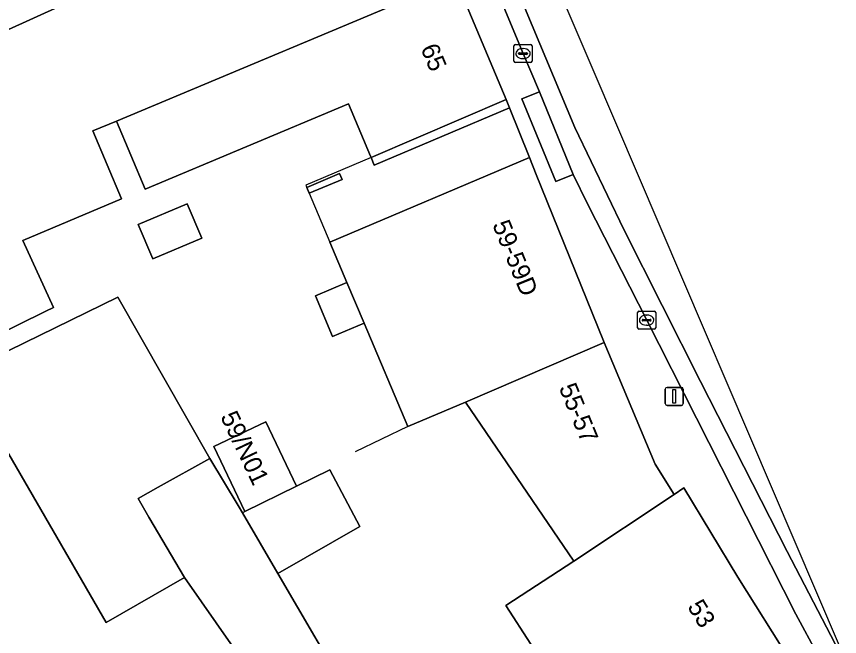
# Model space of a CAD drawing. Extents: x 159371 to 159986, y 382987 to 383597.
# Drawn here: x 159937.11 to 159982.64, y 383297.7 to 383332.01 of the extents above; entities that cross this region are included whole.
import ezdxf

# ---------------------------------------------------------------- set-up
doc = ezdxf.new("R2010")
doc.units = 0
for name, color, linetype in [('IMGEO_Erf', 7, 'Continuous'), ('IMGEO_Kolk', 7, 'Continuous'), ('IMGEO_Lichtmast', 7, 'Continuous'), ('IMGEO_Muur', 7, 'Continuous'), ('IMGEO_Pand', 7, 'Continuous'), ('IMGEO_Pand_nummerreeks', 7, 'Continuous'), ('IMGEO_Pand_overbouw', 7, 'Continuous'), ('IMGEO_Rijbaan_lokaal_gesloten', 7, 'Continuous'), ('IMGEO_Rijbaan_lokaal_open', 7, 'Continuous'), ('IMGEO_Voetpad_open', 7, 'Continuous')]:
    doc.layers.add(name, color=color, linetype=linetype)

msp = doc.modelspace()

# ---------------------------------------------------------------- linework, layer by layer
at = {"layer": 'IMGEO_Erf'}
for points in [[(159929.674, 383336.71), (159932.987, 383329.817), (159933.064, 383329.657), (159939.633, 383332.626)], [(159966.951, 383295.149), (159964.186, 383299.423), (159967.948, 383301.873), (159961.953, 383310.678), (159958.755, 383309.324), (159956.332, 383315.043), (159954.597, 383314.308), (159953.652, 383316.559), (159955.38, 383317.291), (159954.438, 383319.517), (159965.489, 383324.198), (159964.378, 383326.953), (159956.901, 383323.786), (159956.726, 383324.201), (159956.696, 383324.274), (159955.478, 383327.179), (159944.228, 383322.46), (159942.64, 383326.223), (159941.338, 383325.677), (159942.926, 383321.914), (159937.464, 383319.623), (159939.155, 383315.913), (159938.725, 383315.702), (159934.236, 383313.5)], [(159934.071, 383312.263), (159942.713, 383316.486), (159947.811, 383307.547), (159949.364, 383304.957), (159949.605, 383304.544), (159949.745, 383304.614), (159948.027, 383308.209), (159950.905, 383309.585), (159952.605, 383306.029), (159954.438, 383306.935), (159956.105, 383303.788), (159951.562, 383301.19), (159955.785, 383293.954), (159952.607, 383292.1), (159946.404, 383300.967), (159942.065, 383298.484), (159936.196, 383308.615)]]:
    msp.add_lwpolyline(points, dxfattribs=at)
for points in [[(159953.299, 383322.228), (159953.163, 383322.55), (159954.981, 383323.32), (159955.117, 383322.998)], [(159943.845, 383320.503), (159946.558, 383321.648), (159947.362, 383319.744), (159944.649, 383318.599)]]:
    msp.add_lwpolyline(points, close=True, dxfattribs=at)
at = {"layer": 'IMGEO_Kolk'}
for p, q in [((159964.627, 383329.53), (159964.627, 383330.382)), ((159964.702, 383330.456), (159965.554, 383330.456)), ((159965.628, 383330.382), (159965.628, 383329.53)), ((159964.886, 383329.95), (159964.886, 383329.962)), ((159965.324, 383329.913), (159964.926, 383329.913)), ((159964.929, 383329.999), (159965.327, 383329.999)), ((159965.115, 383330.236), (159965.14, 383330.236)), ((159965.37, 383329.962), (159965.37, 383329.95)), ((159965.554, 383329.456), (159964.702, 383329.456)), ((159965.138, 383329.676), (159965.113, 383329.676)), ((159971.466, 383314.783), (159971.466, 383315.635)), ((159971.541, 383315.709), (159972.393, 383315.709)), ((159971.954, 383315.489), (159971.979, 383315.489)), ((159972.467, 383315.635), (159972.467, 383314.783)), ((159971.725, 383315.203), (159971.725, 383315.215)), ((159972.163, 383315.166), (159971.765, 383315.166)), ((159971.768, 383315.252), (159972.166, 383315.252)), ((159971.977, 383314.929), (159971.952, 383314.929)), ((159972.209, 383315.215), (159972.209, 383315.203)), ((159972.393, 383314.709), (159971.541, 383314.709))]:
    msp.add_line(p, q, dxfattribs=at)
for points in [[(159964.627, 383329.53), (159964.627, 383330.382)], [(159964.702, 383330.456), (159965.554, 383330.456)], [(159965.628, 383330.382), (159965.628, 383329.53)], [(159965.554, 383329.456), (159964.702, 383329.456)], [(159971.466, 383314.783), (159971.466, 383315.635)], [(159971.541, 383315.709), (159972.393, 383315.709)], [(159972.467, 383315.635), (159972.467, 383314.783)], [(159972.393, 383314.709), (159971.541, 383314.709)]]:
    msp.add_lwpolyline(points, dxfattribs=at)
for centre, radius, start, end in [((159964.704, 383330.38), 0.0765, 91.552, 178.448), ((159964.704, 383330.38), 0.0765, 91.552, 178.448), ((159965.552, 383330.38), 0.0765, 1.552, 88.448), ((159965.552, 383330.38), 0.0765, 1.552, 88.448), ((159964.926, 383329.959), 0.0403, 85.8775, 175.7526), ((159964.923, 383329.949), 0.0366, 178.938, 274.7102), ((159965.327, 383329.956), 0.043, 264.8664, 352.4533), ((159965.331, 383329.961), 0.0386, 1.7309, 96.639), ((159964.704, 383329.532), 0.0765, 181.552, 268.448), ((159964.704, 383329.532), 0.0765, 181.552, 268.448), ((159965.552, 383329.532), 0.0765, 271.552, 358.448), ((159965.552, 383329.532), 0.0765, 271.552, 358.448), ((159971.543, 383315.633), 0.0765, 91.552, 178.448), ((159971.543, 383315.633), 0.0765, 91.552, 178.448), ((159972.391, 383315.633), 0.0765, 1.552, 88.448), ((159972.391, 383315.633), 0.0765, 1.552, 88.448), ((159971.765, 383315.212), 0.0403, 85.8775, 175.7526), ((159971.762, 383315.202), 0.0366, 178.938, 274.7102), ((159972.166, 383315.209), 0.043, 264.8664, 352.4533), ((159972.17, 383315.214), 0.0386, 1.7309, 96.639), ((159971.543, 383314.785), 0.0765, 181.552, 268.448), ((159971.543, 383314.785), 0.0765, 181.552, 268.448), ((159972.391, 383314.785), 0.0765, 271.552, 358.448), ((159972.391, 383314.785), 0.0765, 271.552, 358.448)]:
    msp.add_arc(centre, radius, start, end, dxfattribs=at)
for centre, major_axis, ratio, start_param, end_param in [((159965.114, 383329.956), (-0.387, 0.002), 0.722429, 4.712389, 7.853982), ((159965.139, 383329.956), (-0.39, 0.002), 0.717154, 1.570796, 4.712389), ((159971.953, 383315.209), (-0.387, 0.002), 0.722429, 4.712389, 7.853982), ((159971.978, 383315.209), (-0.39, 0.002), 0.717154, 1.570796, 4.712389)]:
    msp.add_ellipse(centre, major_axis=major_axis, ratio=ratio, start_param=start_param, end_param=end_param, dxfattribs=at)
at = {"layer": 'IMGEO_Lichtmast'}
for p, q in [((159972.999, 383310.589), (159972.999, 383311.389)), ((159972.999, 383311.389), (159972.999, 383310.589)), ((159973.099, 383311.489), (159973.889, 383311.489)), ((159973.889, 383311.489), (159973.099, 383311.489)), ((159973.989, 383311.389), (159973.989, 383310.589)), ((159973.989, 383310.589), (159973.989, 383311.389)), ((159973.889, 383310.489), (159973.099, 383310.489)), ((159973.099, 383310.489), (159973.889, 383310.489))]:
    msp.add_line(p, q, dxfattribs=at)
msp.add_lwpolyline([(159973.419, 383311.364), (159973.569, 383311.364), (159973.569, 383310.614), (159973.419, 383310.614), (159973.419, 383311.364)], dxfattribs=at)
for centre, start, end in [((159973.099, 383311.389), 90, 180), ((159973.099, 383311.389), 90, 180), ((159973.889, 383311.389), 0, 90), ((159973.889, 383311.389), 360, 90), ((159973.099, 383310.589), 180, 270), ((159973.099, 383310.589), 180, 270), ((159973.889, 383310.589), 270, 0), ((159973.889, 383310.589), 270, 0)]:
    msp.add_arc(centre, 0.1, start, end, dxfattribs=at)
at = {"layer": 'IMGEO_Muur'}
msp.add_lwpolyline([(159958.755, 383309.324), (159955.838, 383307.922)], dxfattribs=at)
at = {"layer": 'IMGEO_Pand'}
for points in [[(159961.392, 383334.091), (159958.438, 383341.13), (159944.843, 383335.234), (159943.863, 383334.809), (159939.54, 383332.832), (159939.633, 383332.626), (159933.064, 383329.657), (159932.987, 383329.817), (159927.534, 383327.309), (159934.236, 383313.5), (159938.725, 383315.702), (159939.155, 383315.913), (159937.464, 383319.623), (159942.926, 383321.914), (159941.338, 383325.677), (159942.64, 383326.223)], [(159964.191, 383327.419), (159961.392, 383334.091), (159942.64, 383326.223), (159944.228, 383322.46), (159955.478, 383327.179), (159956.696, 383324.274), (159956.726, 383324.201)], [(159964.378, 383326.953), (159964.191, 383327.419), (159956.726, 383324.201), (159956.901, 383323.786)], [(159965.863, 383323.269), (159965.489, 383324.198), (159954.438, 383319.517), (159955.38, 383317.291), (159956.332, 383315.043), (159958.755, 383309.324), (159961.953, 383310.678), (159969.612, 383313.966), (159969.264, 383314.829)], [(159955.117, 383322.998), (159954.981, 383323.32), (159953.163, 383322.55), (159953.299, 383322.228)], [(159943.845, 383320.503), (159944.649, 383318.599), (159947.362, 383319.744), (159946.558, 383321.648)], [(159936.196, 383308.615), (159942.065, 383298.484), (159946.404, 383300.967), (159944.439, 383304.314), (159943.837, 383305.341), (159944.953, 383305.96), (159947.811, 383307.547), (159942.713, 383316.486), (159934.071, 383312.263)], [(159961.953, 383310.678), (159967.948, 383301.873), (159973.493, 383305.565), (159972.441, 383307.245), (159969.612, 383313.966)], [(159949.745, 383304.614), (159952.605, 383306.029), (159950.905, 383309.585), (159948.027, 383308.209)], [(159951.562, 383301.19), (159949.605, 383304.544), (159949.364, 383304.957), (159947.811, 383307.547), (159944.953, 383305.96), (159943.837, 383305.341), (159944.439, 383304.314), (159946.404, 383300.967), (159952.607, 383292.1), (159955.785, 383293.954)], [(159952.605, 383306.029), (159949.745, 383304.614), (159949.605, 383304.544), (159951.562, 383301.19), (159956.105, 383303.788), (159954.438, 383306.935)], [(159977.007, 383300.995), (159974.015, 383305.934), (159973.493, 383305.565), (159967.948, 383301.873), (159964.186, 383299.423), (159966.951, 383295.149), (159970.948, 383288.972), (159977.824, 383293.484), (159979.338, 383294.477), (159979.443, 383294.433), (159979.906, 383296.377)]]:
    msp.add_lwpolyline(points, close=True, dxfattribs=at)
at = {"layer": 'IMGEO_Pand_overbouw'}
for points in [[(159956.726, 383324.201), (159953.109, 383322.679), (159953.163, 383322.55), (159954.981, 383323.32), (159955.117, 383322.998), (159953.299, 383322.228), (159954.438, 383319.517), (159965.489, 383324.198), (159964.378, 383326.953), (159956.901, 383323.786)], [(159955.38, 383317.291), (159953.652, 383316.559), (159954.597, 383314.308), (159956.332, 383315.043)]]:
    msp.add_lwpolyline(points, close=True, dxfattribs=at)
at = {"layer": 'IMGEO_Rijbaan_lokaal_gesloten'}
msp.add_lwpolyline([(159955.349, 383356.123), (159945.45, 383379.953), (159944.818, 383381.47), (159943.844, 383381.078), (159943.997, 383380.769), (159949.547, 383367.357), (159955.098, 383353.99), (159959.545, 383343.383), (159965.129, 383329.956), (159966.033, 383327.842), (159967.899, 383323.262), (159968.686, 383321.639), (159971.968, 383315.21), (159980.218, 383298.949), (159981.447, 383296.649), (159982.474, 383297.117), (159982.396, 383297.308), (159979.747, 383302.409), (159974.947, 383311.811), (159970.698, 383320.214), (159967.997, 383325.865)], close=True, dxfattribs=at)
at = {"layer": 'IMGEO_Rijbaan_lokaal_open'}
msp.add_lwpolyline([(159982.637, 383297.191), (159969, 383329.052), (159952.719, 383367.092), (159946.492, 383382.144), (159944.818, 383381.47), (159945.45, 383379.953), (159955.349, 383356.123), (159967.997, 383325.865), (159970.698, 383320.214), (159974.947, 383311.811), (159979.747, 383302.409), (159982.396, 383297.308), (159982.474, 383297.117)], close=True, dxfattribs=at)
at = {"layer": 'IMGEO_Voetpad_open'}
msp.add_lwpolyline([(159961.392, 383334.091), (159964.191, 383327.419), (159964.378, 383326.953), (159965.489, 383324.198), (159965.863, 383323.269), (159969.264, 383314.829), (159969.612, 383313.966), (159972.441, 383307.245), (159973.493, 383305.565), (159974.015, 383305.934), (159977.007, 383300.995), (159979.906, 383296.377), (159979.443, 383294.433), (159981.823, 383295.807), (159981.447, 383296.649), (159980.218, 383298.949), (159971.968, 383315.21), (159968.686, 383321.639), (159967.899, 383323.262), (159966.936, 383322.87), (159965.07, 383327.45), (159966.033, 383327.842), (159965.129, 383329.956), (159959.545, 383343.383)], dxfattribs=at)
for points in [[(159966.033, 383327.842), (159965.07, 383327.45), (159966.936, 383322.87), (159967.899, 383323.262)], [(159955.38, 383317.291), (159953.652, 383316.559), (159954.597, 383314.308), (159956.332, 383315.043)]]:
    msp.add_lwpolyline(points, close=True, dxfattribs=at)

# ---------------------------------------------------------------- texts
at = {"layer": 'IMGEO_Pand_nummerreeks'}
for s, rotation, p in [('65', 292.7577, (159959.448, 383330.248)), ('59-59D', 292.1618, (159963.417, 383320.496)), ('55-57', 292.4136, (159967.098, 383311.471)), ('59/N01', 295.3875, (159948.368, 383309.878)), ('53', 301.4437, (159974.193, 383299.358))]:
    msp.add_text(s, height=1, rotation=rotation, dxfattribs=at).set_placement(p)

doc.saveas('drawing.dxf')
